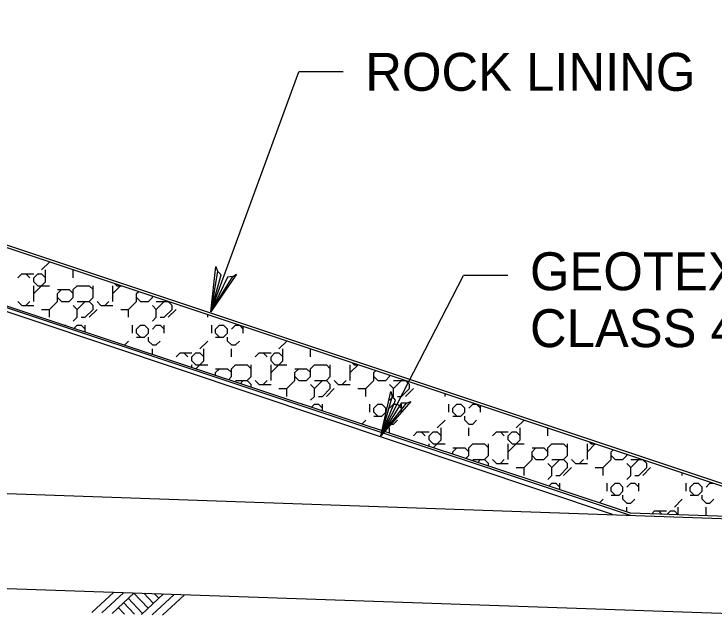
# Model space of a CAD drawing. Extents: x 636462 to 639890, y 299944 to 300538.
# Drawn here: x 638511 to 638566.3, y 300367.1 to 300415 of the extents above; entities that cross this region are included whole.
import ezdxf

# ---------------------------------------------------------------- set-up
doc = ezdxf.new("R2010")
doc.units = 0
doc.layers.add('Default', color=7, linetype='Continuous')

msp = doc.modelspace()

# ---------------------------------------------------------------- linework, layer by layer
at = {"layer": 'Default'}
for p, q in [((638455.666, 300415.029), (638576.237, 300374.838)), ((638526.587, 300391.486), (638533.533, 300410.456)), ((638537.031, 300410.456), (638533.533, 300410.456)), ((638513.218, 300394.803), (638513.842, 300395.428)), ((638513.53, 300393.866), (638513.53, 300394.803)), ((638515.716, 300394.178), (638515.716, 300394.803)), ((638511.344, 300394.178), (638511.656, 300394.491)), ((638511.656, 300394.491), (638512.593, 300394.491)), ((638512.281, 300394.178), (638511.969, 300394.491)), ((638512.593, 300394.178), (638512.905, 300394.491)), ((638512.905, 300394.491), (638513.218, 300394.491)), ((638513.53, 300394.178), (638513.218, 300394.491)), ((638540.015, 300381.679), (638546.538, 300394.365)), ((638550.035, 300394.365), (638546.538, 300394.365)), ((638512.593, 300393.866), (638512.593, 300394.178)), ((638512.905, 300393.554), (638512.593, 300393.866)), ((638512.593, 300392.929), (638513.53, 300393.866)), ((638517.59, 300394.178), (638517.606, 300394.194)), ((638519.151, 300393.554), (638518.965, 300393.74)), ((638512.593, 300392.305), (638512.593, 300393.554)), ((638512.905, 300393.554), (638513.842, 300393.554)), ((638514.467, 300392.929), (638514.779, 300393.242)), ((638514.467, 300393.242), (638515.404, 300393.242)), ((638515.716, 300392.929), (638515.404, 300393.242)), ((638515.716, 300393.242), (638516.028, 300393.554)), ((638515.716, 300392.617), (638515.716, 300393.242)), ((638516.028, 300393.554), (638516.965, 300393.554)), ((638517.278, 300393.242), (638516.965, 300393.554)), ((638517.278, 300392.617), (638517.278, 300393.554)), ((638518.839, 300392.929), (638519.478, 300393.569)), ((638518.839, 300392.305), (638518.839, 300393.554)), ((638519.151, 300393.554), (638519.523, 300393.554)), ((638514.467, 300392.305), (638514.467, 300392.929)), ((638514.779, 300392.305), (638514.467, 300392.617)), ((638515.404, 300392.305), (638515.716, 300392.617)), ((638516.965, 300392.305), (638517.278, 300392.617)), ((638520.713, 300392.929), (638520.883, 300393.1)), ((638520.713, 300392.305), (638520.713, 300392.929)), ((638521.025, 300392.305), (638520.713, 300392.617)), ((638521.65, 300392.305), (638521.962, 300392.617)), ((638521.962, 300392.617), (638521.962, 300392.739)), ((638511.656, 300391.992), (638511.344, 300392.305)), ((638511.969, 300391.992), (638512.281, 300392.305)), ((638513.842, 300391.68), (638514.467, 300392.305)), ((638514.779, 300392.305), (638515.404, 300392.305)), ((638516.028, 300391.68), (638516.653, 300392.305)), ((638516.028, 300392.305), (638516.965, 300392.305)), ((638517.278, 300391.992), (638516.965, 300392.305)), ((638517.902, 300391.992), (638517.59, 300392.305)), ((638518.215, 300391.992), (638518.527, 300392.305)), ((638520.088, 300391.68), (638520.713, 300392.305)), ((638521.025, 300392.305), (638521.65, 300392.305)), ((638522.274, 300391.68), (638522.899, 300392.305)), ((638522.274, 300392.305), (638523.211, 300392.305)), ((638523.211, 300392.305), (638523.224, 300392.318)), ((638523.524, 300391.992), (638523.211, 300392.305)), ((638511.314, 300391.65), (638511.344, 300391.68)), ((638511.656, 300391.992), (638512.593, 300391.992)), ((638513.218, 300391.68), (638513.842, 300391.68)), ((638513.842, 300391.056), (638513.842, 300391.68)), ((638516.028, 300391.68), (638515.716, 300391.992)), ((638516.028, 300391.056), (638516.028, 300391.68)), ((638516.653, 300391.056), (638517.278, 300391.68)), ((638516.965, 300391.056), (638517.59, 300391.68)), ((638517.278, 300391.68), (638517.278, 300391.992)), ((638517.902, 300391.992), (638518.839, 300391.992)), ((638519.464, 300391.68), (638520.088, 300391.68)), ((638520.088, 300391.056), (638520.088, 300391.68)), ((638522.274, 300391.68), (638521.962, 300391.992)), ((638522.274, 300391.056), (638522.274, 300391.68)), ((638522.899, 300391.056), (638523.524, 300391.68)), ((638523.211, 300391.056), (638523.836, 300391.68)), ((638523.524, 300391.68), (638523.524, 300391.992)), ((638524.148, 300391.992), (638524.123, 300392.018)), ((638524.148, 300391.992), (638524.198, 300391.992)), ((638515.716, 300390.743), (638516.028, 300391.056)), ((638516.341, 300391.056), (638516.653, 300391.056)), ((638521.962, 300390.743), (638522.274, 300391.056)), ((638522.587, 300391.056), (638522.899, 300391.056)), ((638526.334, 300391.056), (638526.334, 300391.279)), ((638514.988, 300390.431), (638515.092, 300390.431)), ((638515.143, 300390.379), (638515.092, 300390.431)), ((638515.769, 300390.172), (638516.028, 300390.431)), ((638516.028, 300390.431), (638516.341, 300390.431)), ((638516.653, 300390.119), (638516.341, 300390.431)), ((638516.653, 300389.878), (638516.653, 300390.431)), ((638520.401, 300389.806), (638520.401, 300390.431)), ((638520.713, 300390.119), (638521.025, 300390.431)), ((638521.025, 300390.431), (638521.337, 300390.431)), ((638521.65, 300390.119), (638521.337, 300390.431)), ((638521.962, 300390.119), (638522.274, 300390.431)), ((638522.274, 300390.431), (638522.587, 300390.431)), ((638522.899, 300390.119), (638522.587, 300390.431)), ((638522.899, 300389.806), (638522.899, 300390.431)), ((638526.647, 300389.806), (638526.647, 300390.431)), ((638526.959, 300390.119), (638527.271, 300390.431)), ((638527.271, 300390.431), (638527.583, 300390.431)), ((638527.896, 300390.119), (638527.583, 300390.431)), ((638528.208, 300390.119), (638528.52, 300390.431)), ((638528.52, 300390.431), (638528.833, 300390.431)), ((638529.145, 300390.119), (638528.833, 300390.431)), ((638520.713, 300389.806), (638520.713, 300390.119)), ((638521.65, 300389.806), (638521.65, 300390.119)), ((638526.959, 300389.806), (638526.959, 300390.119)), ((638527.896, 300389.806), (638527.896, 300390.119)), ((638529.145, 300389.806), (638529.145, 300390.341)), ((638521.025, 300389.494), (638520.713, 300389.806)), ((638520.713, 300389.494), (638521.337, 300389.494)), ((638521.337, 300389.494), (638521.65, 300389.806)), ((638521.65, 300389.182), (638521.65, 300389.494)), ((638527.271, 300389.494), (638526.959, 300389.806)), ((638526.959, 300389.494), (638527.583, 300389.494)), ((638527.583, 300389.494), (638527.896, 300389.806)), ((638527.896, 300389.182), (638527.896, 300389.494)), ((638519.755, 300388.849), (638520.088, 300389.182)), ((638521.962, 300388.869), (638521.65, 300389.182)), ((638521.962, 300388.869), (638522.274, 300388.869)), ((638522.274, 300388.869), (638522.587, 300389.182)), ((638525.71, 300388.557), (638526.334, 300389.182)), ((638528.208, 300388.869), (638527.896, 300389.182)), ((638528.208, 300388.869), (638528.52, 300388.869)), ((638528.52, 300388.869), (638528.833, 300389.182)), ((638531.956, 300388.557), (638532.58, 300389.182)), ((638521.962, 300388.116), (638521.962, 300388.557)), ((638523.836, 300387.933), (638524.148, 300388.245)), ((638524.148, 300388.245), (638525.085, 300388.245)), ((638524.773, 300387.933), (638524.46, 300388.245)), ((638525.085, 300387.933), (638525.397, 300388.245)), ((638525.397, 300388.245), (638525.71, 300388.245)), ((638526.022, 300387.933), (638525.71, 300388.245)), ((638526.022, 300387.62), (638526.022, 300388.557)), ((638528.208, 300387.933), (638528.208, 300388.557)), ((638530.082, 300387.933), (638530.394, 300388.245)), ((638530.394, 300388.245), (638531.331, 300388.245)), ((638531.019, 300387.933), (638530.706, 300388.245)), ((638531.331, 300387.933), (638531.643, 300388.245)), ((638531.643, 300388.245), (638531.956, 300388.245)), ((638532.268, 300387.933), (638531.956, 300388.245)), ((638532.268, 300387.62), (638532.268, 300388.557)), ((638534.454, 300387.933), (638534.454, 300388.557)), ((638525.085, 300387.62), (638525.085, 300387.933)), ((638525.397, 300387.308), (638525.085, 300387.62)), ((638525.382, 300386.981), (638526.022, 300387.62)), ((638531.331, 300387.62), (638531.331, 300387.933)), ((638531.643, 300387.308), (638531.331, 300387.62)), ((638531.331, 300386.683), (638532.268, 300387.62)), ((638536.328, 300387.933), (638536.335, 300387.94)), ((638525.085, 300387.079), (638525.085, 300387.308)), ((638525.397, 300387.308), (638526.334, 300387.308)), ((638528.208, 300386.996), (638528.52, 300387.308)), ((638528.52, 300387.308), (638529.457, 300387.308)), ((638529.769, 300386.996), (638529.457, 300387.308)), ((638529.769, 300386.371), (638529.769, 300387.308)), ((638531.331, 300386.059), (638531.331, 300387.308)), ((638531.643, 300387.308), (638532.58, 300387.308)), ((638534.454, 300386.996), (638534.766, 300387.308)), ((638534.766, 300387.308), (638535.703, 300387.308)), ((638536.015, 300386.996), (638535.703, 300387.308)), ((638536.015, 300386.371), (638536.015, 300387.308)), ((638537.577, 300386.683), (638538.208, 300387.314)), ((638537.577, 300386.059), (638537.577, 300387.308)), ((638537.889, 300387.308), (638537.72, 300387.477)), ((638537.889, 300387.308), (638538.226, 300387.308)), ((638526.959, 300386.683), (638527.271, 300386.996)), ((638526.959, 300386.996), (638527.896, 300386.996)), ((638526.959, 300386.457), (638526.959, 300386.683)), ((638528.208, 300386.683), (638527.896, 300386.996)), ((638528.208, 300386.371), (638528.208, 300386.996)), ((638533.205, 300386.683), (638533.517, 300386.996)), ((638533.205, 300386.996), (638534.142, 300386.996)), ((638533.205, 300386.059), (638533.205, 300386.683)), ((638534.454, 300386.683), (638534.142, 300386.996)), ((638534.454, 300386.371), (638534.454, 300386.996)), ((638539.451, 300386.683), (638539.612, 300386.845)), ((638539.451, 300386.059), (638539.451, 300386.683)), ((638527.962, 300386.125), (638528.208, 300386.371)), ((638528.52, 300386.059), (638529.457, 300386.059)), ((638528.899, 300385.813), (638529.145, 300386.059)), ((638529.457, 300386.059), (638529.769, 300386.371)), ((638529.769, 300385.746), (638529.457, 300386.059)), ((638530.394, 300385.746), (638530.082, 300386.059)), ((638530.706, 300385.746), (638531.019, 300386.059)), ((638532.58, 300385.434), (638533.205, 300386.059)), ((638533.517, 300386.059), (638533.205, 300386.371)), ((638533.517, 300386.059), (638534.142, 300386.059)), ((638534.142, 300386.059), (638534.454, 300386.371)), ((638534.766, 300385.434), (638535.391, 300386.059)), ((638534.766, 300386.059), (638535.703, 300386.059)), ((638535.703, 300386.059), (638536.015, 300386.371)), ((638536.015, 300385.746), (638535.703, 300386.059)), ((638536.64, 300385.746), (638536.328, 300386.059)), ((638536.952, 300385.746), (638537.265, 300386.059)), ((638538.826, 300385.434), (638539.451, 300386.059)), ((638539.763, 300386.059), (638539.451, 300386.371)), ((638539.763, 300386.059), (638540.388, 300386.059)), ((638540.388, 300386.059), (638540.7, 300386.371)), ((638540.7, 300386.371), (638540.7, 300386.482)), ((638541.012, 300385.434), (638541.637, 300386.059)), ((638541.012, 300386.059), (638541.949, 300386.059)), ((638541.949, 300386.059), (638541.953, 300386.063)), ((638542.261, 300385.746), (638541.949, 300386.059)), ((638529.769, 300385.524), (638529.769, 300385.746)), ((638530.072, 300385.424), (638530.082, 300385.434)), ((638530.394, 300385.746), (638531.331, 300385.746)), ((638531.956, 300385.434), (638532.58, 300385.434)), ((638532.58, 300384.81), (638532.58, 300385.434)), ((638534.766, 300385.434), (638534.454, 300385.746)), ((638534.766, 300384.81), (638534.766, 300385.434)), ((638535.391, 300384.81), (638536.015, 300385.434)), ((638535.703, 300384.81), (638536.328, 300385.434)), ((638536.015, 300385.434), (638536.015, 300385.746)), ((638536.64, 300385.746), (638537.577, 300385.746)), ((638538.201, 300385.434), (638538.826, 300385.434)), ((638538.826, 300384.81), (638538.826, 300385.434)), ((638541.012, 300385.434), (638540.7, 300385.746)), ((638541.012, 300384.81), (638541.012, 300385.434)), ((638541.637, 300384.81), (638542.261, 300385.434)), ((638541.949, 300384.81), (638542.574, 300385.434)), ((638542.261, 300385.434), (638542.261, 300385.746)), ((638542.886, 300385.746), (638542.878, 300385.755)), ((638542.886, 300385.746), (638542.902, 300385.746)), ((638545.072, 300384.81), (638545.072, 300385.022)), ((638534.454, 300384.497), (638534.766, 300384.81)), ((638535.079, 300384.81), (638535.391, 300384.81)), ((638540.7, 300384.497), (638541.012, 300384.81)), ((638541.324, 300384.81), (638541.637, 300384.81)), ((638533.805, 300384.185), (638533.829, 300384.185)), ((638533.842, 300384.173), (638533.829, 300384.185)), ((638534.527, 300383.945), (638534.766, 300384.185)), ((638534.766, 300384.185), (638535.079, 300384.185)), ((638535.391, 300383.873), (638535.079, 300384.185)), ((638535.391, 300383.659), (638535.391, 300384.185)), ((638539.138, 300383.56), (638539.138, 300384.185)), ((638539.451, 300383.873), (638539.763, 300384.185)), ((638539.451, 300383.56), (638539.451, 300383.873)), ((638539.763, 300384.185), (638540.075, 300384.185)), ((638540.388, 300383.873), (638540.075, 300384.185)), ((638540.388, 300383.56), (638540.388, 300383.873)), ((638540.7, 300383.873), (638541.012, 300384.185)), ((638541.012, 300384.185), (638541.324, 300384.185)), ((638541.637, 300383.873), (638541.324, 300384.185)), ((638541.637, 300383.56), (638541.637, 300384.185)), ((638545.384, 300383.56), (638545.384, 300384.185)), ((638545.697, 300383.873), (638546.009, 300384.185)), ((638545.697, 300383.56), (638545.697, 300383.873)), ((638546.009, 300384.185), (638546.321, 300384.185)), ((638546.633, 300383.873), (638546.321, 300384.185)), ((638546.633, 300383.56), (638546.633, 300383.873)), ((638546.946, 300383.873), (638547.258, 300384.185)), ((638547.258, 300384.185), (638547.57, 300384.185)), ((638547.883, 300383.873), (638547.57, 300384.185)), ((638547.883, 300383.56), (638547.883, 300384.083)), ((638539.763, 300383.248), (638539.451, 300383.56)), ((638539.451, 300383.248), (638540.075, 300383.248)), ((638540.075, 300383.248), (638540.388, 300383.56)), ((638540.388, 300382.936), (638540.388, 300383.248)), ((638546.009, 300383.248), (638545.697, 300383.56)), ((638545.697, 300383.248), (638546.321, 300383.248)), ((638546.321, 300383.248), (638546.633, 300383.56)), ((638546.633, 300382.936), (638546.633, 300383.248)), ((638538.513, 300382.622), (638538.826, 300382.936)), ((638540.7, 300382.624), (638540.388, 300382.936)), ((638541.012, 300382.624), (638541.324, 300382.936)), ((638544.447, 300382.311), (638545.072, 300382.936)), ((638546.946, 300382.624), (638546.633, 300382.936)), ((638547.258, 300382.624), (638547.57, 300382.936)), ((638550.693, 300382.311), (638551.318, 300382.936)), ((638540.7, 300382.624), (638541.012, 300382.624)), ((638540.7, 300381.896), (638540.7, 300382.311)), ((638544.76, 300381.374), (638544.76, 300382.311)), ((638546.946, 300382.624), (638547.258, 300382.624)), ((638546.946, 300381.687), (638546.946, 300382.311)), ((638551.006, 300381.374), (638551.006, 300382.311)), ((638553.192, 300381.687), (638553.192, 300382.31)), ((638542.574, 300381.687), (638542.886, 300381.999)), ((638542.886, 300381.999), (638543.823, 300381.999)), ((638543.511, 300381.687), (638543.198, 300381.999)), ((638543.823, 300381.687), (638544.135, 300381.999)), ((638543.823, 300381.374), (638543.823, 300381.687)), ((638544.135, 300381.999), (638544.447, 300381.999)), ((638544.76, 300381.687), (638544.447, 300381.999)), ((638548.82, 300381.687), (638549.132, 300381.999)), ((638549.132, 300381.999), (638550.069, 300381.999)), ((638549.756, 300381.687), (638549.444, 300381.999)), ((638550.069, 300381.687), (638550.381, 300381.999)), ((638550.069, 300381.374), (638550.069, 300381.687)), ((638550.381, 300381.999), (638550.693, 300381.999)), ((638551.006, 300381.687), (638550.693, 300381.999)), ((638544.135, 300381.062), (638543.823, 300381.374)), ((638543.823, 300380.86), (638543.823, 300381.062)), ((638544.135, 300381.062), (638545.072, 300381.062)), ((638544.14, 300380.754), (638544.76, 300381.374)), ((638546.946, 300380.75), (638547.258, 300381.062)), ((638547.258, 300381.062), (638548.195, 300381.062)), ((638548.507, 300380.75), (638548.195, 300381.062)), ((638548.507, 300380.125), (638548.507, 300381.062)), ((638550.381, 300381.062), (638550.069, 300381.374)), ((638550.069, 300380.437), (638551.006, 300381.374)), ((638550.069, 300379.813), (638550.069, 300381.062)), ((638550.381, 300381.062), (638551.318, 300381.062)), ((638553.192, 300380.75), (638553.504, 300381.062)), ((638553.504, 300381.062), (638554.441, 300381.062)), ((638554.753, 300380.75), (638554.441, 300381.062)), ((638554.753, 300380.125), (638554.753, 300381.062)), ((638556.315, 300379.813), (638556.315, 300381.062)), ((638556.315, 300380.437), (638556.937, 300381.06)), ((638556.627, 300381.062), (638556.475, 300381.214)), ((638556.627, 300381.062), (638556.93, 300381.062)), ((638545.697, 300380.437), (638546.009, 300380.75)), ((638545.697, 300380.75), (638546.633, 300380.75)), ((638545.697, 300380.238), (638545.697, 300380.437)), ((638546.946, 300380.437), (638546.633, 300380.75)), ((638546.946, 300380.125), (638546.946, 300380.75)), ((638551.943, 300380.437), (638552.255, 300380.75)), ((638551.943, 300380.75), (638552.879, 300380.75)), ((638551.943, 300379.813), (638551.943, 300380.437)), ((638553.192, 300380.437), (638552.879, 300380.75)), ((638553.192, 300380.125), (638553.192, 300380.75)), ((638558.188, 300380.437), (638558.342, 300380.591)), ((638558.188, 300379.813), (638558.188, 300380.437)), ((638546.719, 300379.898), (638546.946, 300380.125)), ((638548.195, 300379.813), (638548.507, 300380.125)), ((638552.255, 300379.813), (638551.943, 300380.125)), ((638552.879, 300379.813), (638553.192, 300380.125)), ((638554.441, 300379.813), (638554.753, 300380.125)), ((638558.501, 300379.813), (638558.188, 300380.125)), ((638559.125, 300379.813), (638559.438, 300380.125)), ((638559.438, 300380.125), (638559.438, 300380.224)), ((638547.258, 300379.813), (638548.195, 300379.813)), ((638547.657, 300379.587), (638547.883, 300379.813)), ((638548.507, 300379.501), (638548.195, 300379.813)), ((638548.507, 300379.305), (638548.507, 300379.501)), ((638549.132, 300379.501), (638548.82, 300379.813)), ((638549.132, 300379.501), (638550.069, 300379.501)), ((638549.444, 300379.501), (638549.756, 300379.813)), ((638551.318, 300379.188), (638551.943, 300379.813)), ((638552.255, 300379.813), (638552.879, 300379.813)), ((638553.504, 300379.188), (638553.192, 300379.501)), ((638553.504, 300379.188), (638554.129, 300379.813)), ((638553.504, 300379.813), (638554.441, 300379.813)), ((638554.753, 300379.501), (638554.441, 300379.813)), ((638554.753, 300379.188), (638554.753, 300379.501)), ((638555.378, 300379.501), (638555.065, 300379.813)), ((638555.378, 300379.501), (638556.315, 300379.501)), ((638555.69, 300379.501), (638556.002, 300379.813)), ((638557.564, 300379.188), (638558.188, 300379.813)), ((638558.501, 300379.813), (638559.125, 300379.813)), ((638559.75, 300379.188), (638559.438, 300379.501)), ((638559.75, 300379.188), (638560.375, 300379.813)), ((638559.75, 300379.813), (638560.67, 300379.813)), ((638560.999, 300379.501), (638560.695, 300379.805)), ((638560.999, 300379.188), (638560.999, 300379.501)), ((638550.693, 300379.188), (638551.318, 300379.188)), ((638551.318, 300378.564), (638551.318, 300379.188)), ((638553.504, 300378.564), (638553.504, 300379.188)), ((638554.129, 300378.564), (638554.753, 300379.188)), ((638554.441, 300378.564), (638555.065, 300379.188)), ((638556.939, 300379.188), (638557.564, 300379.188)), ((638557.564, 300378.564), (638557.564, 300379.188)), ((638559.75, 300378.564), (638559.75, 300379.188)), ((638560.375, 300378.564), (638560.999, 300379.188)), ((638560.687, 300378.564), (638561.311, 300379.188)), ((638470.52, 300378.53), (638582.339, 300374.625)), ((638553.192, 300378.251), (638553.504, 300378.564)), ((638553.816, 300378.564), (638554.129, 300378.564)), ((638559.438, 300378.251), (638559.75, 300378.564)), ((638560.062, 300378.564), (638560.375, 300378.564)), ((638563.81, 300378.564), (638563.81, 300378.764)), ((638553.284, 300377.719), (638553.504, 300377.939)), ((638553.504, 300377.939), (638553.816, 300377.939)), ((638554.129, 300377.627), (638553.816, 300377.939)), ((638554.129, 300377.439), (638554.129, 300377.939)), ((638557.876, 300377.314), (638557.876, 300377.939)), ((638558.188, 300377.627), (638558.501, 300377.939)), ((638558.501, 300377.939), (638558.813, 300377.939)), ((638559.125, 300377.627), (638558.813, 300377.939)), ((638559.438, 300377.627), (638559.75, 300377.939)), ((638559.75, 300377.939), (638560.062, 300377.939)), ((638560.375, 300377.627), (638560.062, 300377.939)), ((638560.375, 300377.314), (638560.375, 300377.939)), ((638564.122, 300377.314), (638564.122, 300377.939)), ((638564.434, 300377.627), (638564.747, 300377.939)), ((638564.747, 300377.939), (638565.059, 300377.939)), ((638565.371, 300377.627), (638565.059, 300377.939)), ((638565.684, 300377.627), (638565.996, 300377.939)), ((638565.996, 300377.939), (638566.281, 300377.939)), ((638558.188, 300377.314), (638558.188, 300377.627)), ((638558.501, 300377.002), (638558.188, 300377.314)), ((638558.813, 300377.002), (638559.125, 300377.314)), ((638559.125, 300377.314), (638559.125, 300377.627)), ((638564.434, 300377.314), (638564.434, 300377.627)), ((638564.747, 300377.002), (638564.434, 300377.314)), ((638565.059, 300377.002), (638565.371, 300377.314)), ((638565.371, 300377.314), (638565.371, 300377.627)), ((638557.27, 300376.396), (638557.564, 300376.69)), ((638558.188, 300377.002), (638558.813, 300377.002)), ((638559.125, 300376.69), (638559.125, 300377.002)), ((638559.438, 300376.378), (638559.125, 300376.69)), ((638559.75, 300376.378), (638560.062, 300376.69)), ((638563.185, 300376.065), (638563.81, 300376.69)), ((638564.434, 300377.002), (638565.059, 300377.002)), ((638565.371, 300376.69), (638565.371, 300377.002)), ((638565.684, 300376.378), (638565.371, 300376.69)), ((638565.996, 300376.378), (638566.308, 300376.69)), ((638559.438, 300376.378), (638559.75, 300376.378)), ((638559.438, 300375.677), (638559.438, 300376.065)), ((638563.497, 300375.448), (638563.497, 300376.065)), ((638565.684, 300376.378), (638565.996, 300376.378)), ((638565.684, 300375.441), (638565.684, 300376.065)), ((638561.393, 300375.523), (638561.624, 300375.753)), ((638561.624, 300375.753), (638562.561, 300375.753)), ((638562.195, 300375.494), (638561.936, 300375.753)), ((638562.6, 300375.48), (638562.873, 300375.753)), ((638562.873, 300375.753), (638563.185, 300375.753)), ((638563.49, 300375.448), (638563.185, 300375.753)), ((638470.258, 300371.04), (638582.078, 300367.135)), ((638517.186, 300367.718), (638518.915, 300369.332)), ((638517.968, 300367.69), (638519.708, 300369.313)), ((638518.777, 300367.662), (638520.515, 300369.285)), ((638520.061, 300368.859), (638521.179, 300367.659)), ((638520.48, 300369.286), (638521.625, 300368.058)), ((638521.104, 300367.581), (638522.854, 300369.211)), ((638521.289, 300369.258), (638522.034, 300368.457)), ((638521.959, 300367.551), (638523.679, 300369.155)), ((638522.107, 300369.229), (638522.462, 300368.848)), ((638522.768, 300367.523), (638524.489, 300369.127)), ((638519.688, 300368.513), (638520.538, 300367.6)), ((638519.271, 300368.122), (638519.754, 300367.601))]:
    msp.add_line(p, q, dxfattribs=at)
for points in [[(638409.46, 300407.019), (638417.6, 300402.288), (638478.297, 300402.288), (638558.272, 300375.493)], [(638417.651, 300402.537), (638434.429, 300402.537), (638478.328, 300402.537), (638559.69, 300375.416)], [(638528.31, 300394.294), (638528.613, 300394.468), (638526.587, 300391.486), (638528.31, 300394.294), (638527.892, 300394.239), (638526.587, 300391.486), (638527.399, 300394.416), (638527.111, 300394.717), (638526.587, 300391.486), (638526.972, 300395.071), (638527.111, 300394.717)], [(638542.044, 300384.273), (638542.365, 300384.412), (638540.015, 300381.679), (638542.044, 300384.273), (638541.623, 300384.267), (638540.015, 300381.679), (638541.153, 300384.498), (638540.901, 300384.83), (638540.015, 300381.679), (638540.802, 300385.197), (638540.901, 300384.83)]]:
    msp.add_lwpolyline(points, dxfattribs=at)
msp.add_lwpolyline([(638409.872, 300407.166), (638479.046, 300407.071), (638574.957, 300375.042), (638559.723, 300375.582), (638478.369, 300402.586), (638417.7, 300402.605)], close=True, dxfattribs=at)

# ---------------------------------------------------------------- texts
for s, p in [('ROCK LINING', (638538.779, 300408.957)), ('GEOTEXTILE,', (638551.784, 300393.196)), ('CLASS 4, TYPE A', (638551.784, 300388.699))]:
    msp.add_text(s, height=2.99804, dxfattribs=at).set_placement(p)

doc.saveas('drawing.dxf')
